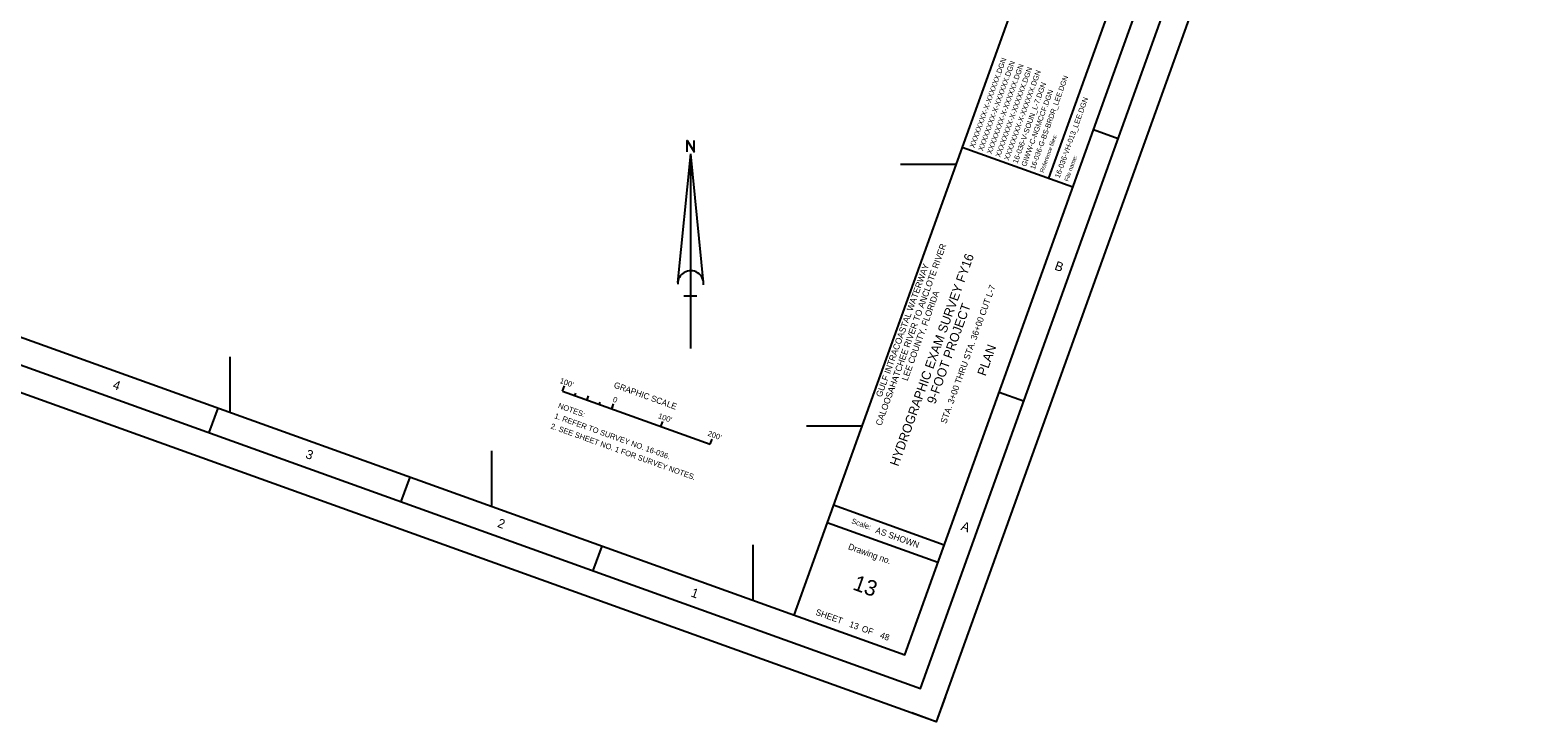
# Model space of a CAD drawing. Extents: x 612209 to 617500, y 780934 to 785622.
# Drawn here: x 614617 to 617500, y 780934 to 782256 of the extents above; entities that cross this region are included whole.
import ezdxf

# ---------------------------------------------------------------- set-up
doc = ezdxf.new("R2010")
doc.units = 0
for name, color, linetype in [('G-ANNO-NPLT', 7, 'Continuous'), ('G-ANNO-TEXT-DRWG', 7, 'Continuous'), ('G-ANNO-TEXT-PROJ', 7, 'Continuous'), ('G-ANNO-TEXT-TTLB', 7, 'Continuous'), ('G-ANNO-TTLB', 7, 'Continuous'), ('V-ANNO-NOTE', 7, 'Continuous'), ('V-ANNO-SYMB', 7, 'Continuous'), ('V-TOPO-COOR-STAT', 7, 'Continuous')]:
    doc.layers.add(name, color=color, linetype=linetype)

msp = doc.modelspace()

# ---------------------------------------------------------------- linework, layer by layer
at = {"layer": 'G-ANNO-NPLT'}
msp.add_lwpolyline([(613359.5, 785622.2), (617500, 784133.6), (616349.7, 780934.1), (612209.2, 782422.8)], close=True, dxfattribs=at)
msp.add_lwpolyline([(616366.8, 780981.1), (616349.9, 780934.1), (616302.8, 780951)], dxfattribs=at)
at = {"layer": 'G-ANNO-TTLB'}
for p, q in [((617160.3, 784149.5), (616077.7, 781138.2)), ((616683.6, 782304.1), (616564.7, 781973.4)), ((616697.4, 782048.8), (616650.3, 782065.8)), ((616399.4, 782032.9), (616611.1, 781956.8)), ((616516.9, 781547), (616469.9, 781563.9)), ((614959.8, 781487), (614976.7, 781534)), ((615326.8, 781355), (615343.7, 781402.1)), ((616153.4, 781348.8), (616365.2, 781272.6)), ((616141.3, 781315.2), (616353.1, 781239.1)), ((615693.8, 781223.1), (615710.7, 781270.1))]:
    msp.add_line(p, q, dxfattribs=at)
for points in [[(612273.2, 782452.9), (616319.6, 780998.1), (617436.1, 784103.5), (613389.7, 785558.3)], [(617372.1, 784073.3), (613490.4, 785468.9), (612407.7, 782457.7), (616289.5, 781062.1)]]:
    msp.add_lwpolyline(points, close=True, dxfattribs=at)
at = {"layer": 'V-ANNO-NOTE'}
for p, q in [((615635.3, 781566.3), (615638.8, 781576.1)), ((615635.3, 781566.3), (615917.6, 781464.8)), ((615658.8, 781557.8), (615660.4, 781562.3)), ((615682.3, 781549.4), (615685.2, 781557.4)), ((615705.8, 781540.9), (615707.5, 781545.4)), ((615729.4, 781532.4), (615732.9, 781542.3)), ((615729.4, 781532.4), (615732.9, 781542.3)), ((615729.4, 781532.4), (615731.1, 781537.1)), ((615823.5, 781498.6), (615827, 781508.4)), ((615917.6, 781464.8), (615921.1, 781474.6))]:
    msp.add_line(p, q, dxfattribs=at)
at = {"layer": 'V-ANNO-SYMB'}
for p, q in [((615855.6, 781774.1), (615880.3, 782019.8)), ((615880.3, 781647.5), (615880.3, 782019.8)), ((615905, 781774.1), (615880.3, 782019.8)), ((615892.1, 781748.1), (615867.2, 781748.1))]:
    msp.add_line(p, q, dxfattribs=at)
msp.add_lwpolyline([(615873.4, 782023.8), (615873.4, 782045.6), (615886.9, 782023.8), (615886.9, 782045.6)], dxfattribs=at)
msp.add_arc((615880.3, 781771.6), 24.8, 355.2984, 182.0673, dxfattribs=at)
at = {"layer": 'V-TOPO-COOR-STAT'}
for p, q in [((616281.3, 782000), (616387.5, 782000)), ((615000, 781525.7), (615000, 781631.9)), ((616101.5, 781500), (616207.8, 781500)), ((615500, 781345.9), (615500, 781452.2)), ((616000, 781166.1), (616000, 781272.4))]:
    msp.add_line(p, q, dxfattribs=at)

# ---------------------------------------------------------------- texts
at = {"layer": 'G-ANNO-TEXT-DRWG'}
for s, height, rotation, p in [('XXXXXXXX-X-XXXXXX.DGN', 10, 70.2251, (616422.6, 782030.2)), ('XXXXXXXX-X-XXXXXX.DGN', 10, 70.2251, (616439.1, 782024.3)), ('XXXXXXXX-X-XXXXXX.DGN', 10, 70.2251, (616455.6, 782018.4)), ('XXXXXXXX-X-XXXXXX.DGN', 10, 70.2251, (616472, 782012.5)), ('XXXXXXXX-X-XXXXXX.DGN', 10, 70.2251, (616488.5, 782006.5)), ('16-036-V-SOUN_L-7.DGN', 10, 70.2251, (616505, 782000.6)), ('GIWW-C-NGMCCF.DGN', 10, 70.2251, (616521.4, 781994.7)), ('16-036-VH-013_LEE.DGN', 10, 70.2251, (616585.5, 781972.8)), ('STA. 3+00 THRU STA. 36+00 CUT L-7 ', 12, 70.2251, (616368.7, 781503.1)), ('PLAN', 17.5, 70.2251, (616444.1, 781593.9)), ('13', 30, 340.2251, (616188.3, 781187.5)), (' 13          48', 12, 340.2251, (616178.1, 781117.5))]:
    msp.add_text(s, height=height, rotation=rotation, dxfattribs=at).set_placement(p)
at = {"layer": 'G-ANNO-TEXT-PROJ'}
for s, height, p in [('16-036-G-BS-BRDR_LEE.DGN', 9.8, (616538.2, 781989.1)), ('CALOOSAHATCHEE RIVER TO ANCLOTE RIVER', 12, (616244.7, 781499.1)), ('HYDROGRAPHIC EXAM SURVEY FY16', 17.5, (616277, 781421.4)), ('GULF INTRACOASTAL WATERWAY', 12, (616245.2, 781553.8)), ('LEE COUNTY, FLORIDA', 12, (616294.7, 781585)), ('9-FOOT PROJECT', 17.5, (616347.7, 781540.3))]:
    msp.add_text(s, height=height, rotation=70.2251, dxfattribs=at).set_placement(p)
at = {"layer": 'G-ANNO-TEXT-TTLB'}
for s, height, rotation, p in [('Reference files:', 8, 70.2251, (616554.9, 781983.2)), ('File name:', 8, 70.2251, (616602, 781966.5)), ('Scale:', 10, 340.2251, (616186.8, 781314.1)), ('AS SHOWN', 12, 340.2251, (616232.5, 781295.6)), ('Drawing no.', 12, 340.2251, (616180.3, 781264.3)), ('SHEET         OF', 12, 340.2251, (616117.9, 781139.1))]:
    msp.add_text(s, height=height, rotation=rotation, dxfattribs=at).set_placement(p)
at = {"layer": 'G-ANNO-TTLB'}
for s, p in [('B', (616574.6, 781799)), ('4', (614773.8, 781571.6)), ('3', (615142.5, 781439)), ('2', (615509.3, 781307.1)), ('A', (616395.7, 781301.4)), ('1', (615879.3, 781174.1))]:
    msp.add_text(s, height=17.5, rotation=340.2251, dxfattribs=at).set_placement(p)
at = {"layer": 'V-ANNO-NOTE'}
for s, height, p in [("100'", 10.42, (615628.9, 781582.1)), ('GRAPHIC SCALE', 11.666, (615732.2, 781573.4)), ('NOTES:', 10.42, (615625.7, 781534.4)), ('0', 10.4, (615730.4, 781546.3)), ('2. SEE SHEET NO. 1 FOR SURVEY NOTES.', 10.416, (615611.6, 781495.2)), ('1. REFER TO SURVEY NO. 16-036.', 10.416, (615618.6, 781514.8)), ("100'", 10.42, (615817, 781514.9)), ("200'", 10.42, (615911.8, 781481.4))]:
    msp.add_text(s, height=height, rotation=340.2251, dxfattribs=at).set_placement(p)

doc.saveas('drawing.dxf')
